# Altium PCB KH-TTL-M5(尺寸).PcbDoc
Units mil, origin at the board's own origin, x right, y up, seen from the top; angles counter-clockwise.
Board outline 6000 x 4000 mil, 2 copper layers (Top Layer, Bottom Layer); 2 components, 28 nets, 12 pads, 0 vias.
Unrouted connection lines stored in the file: 3.
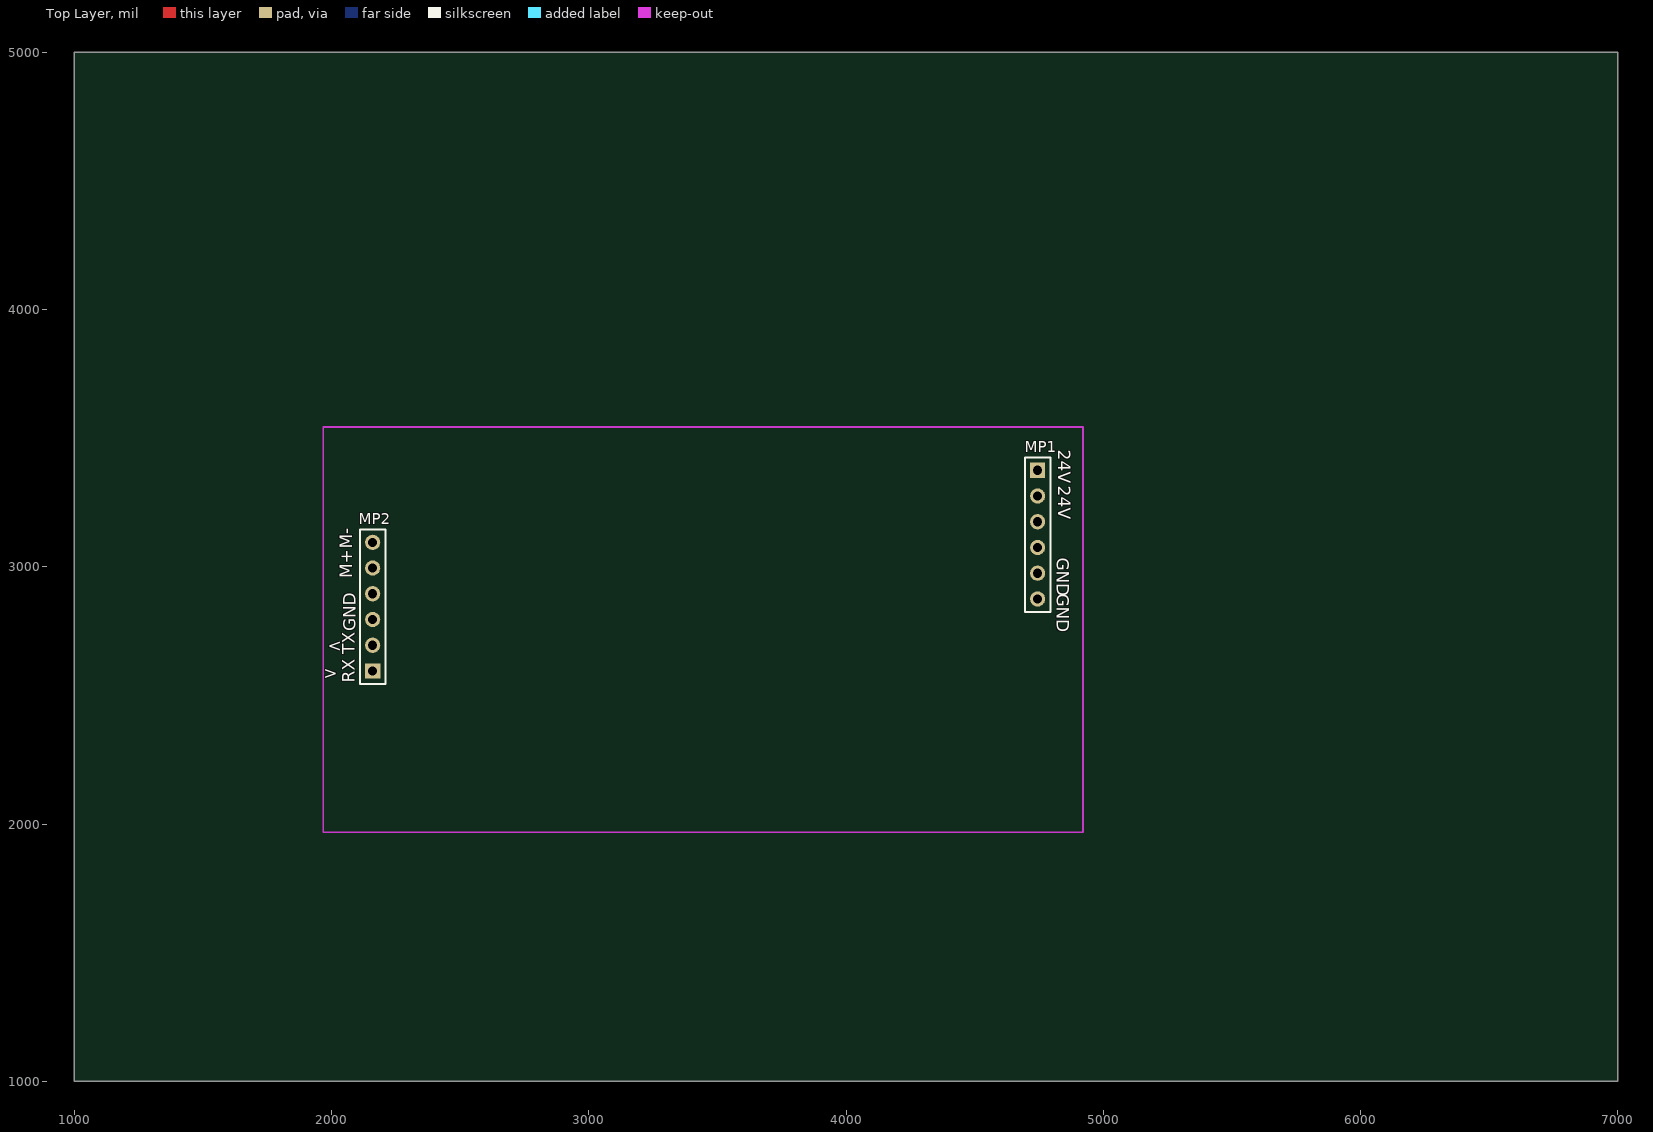
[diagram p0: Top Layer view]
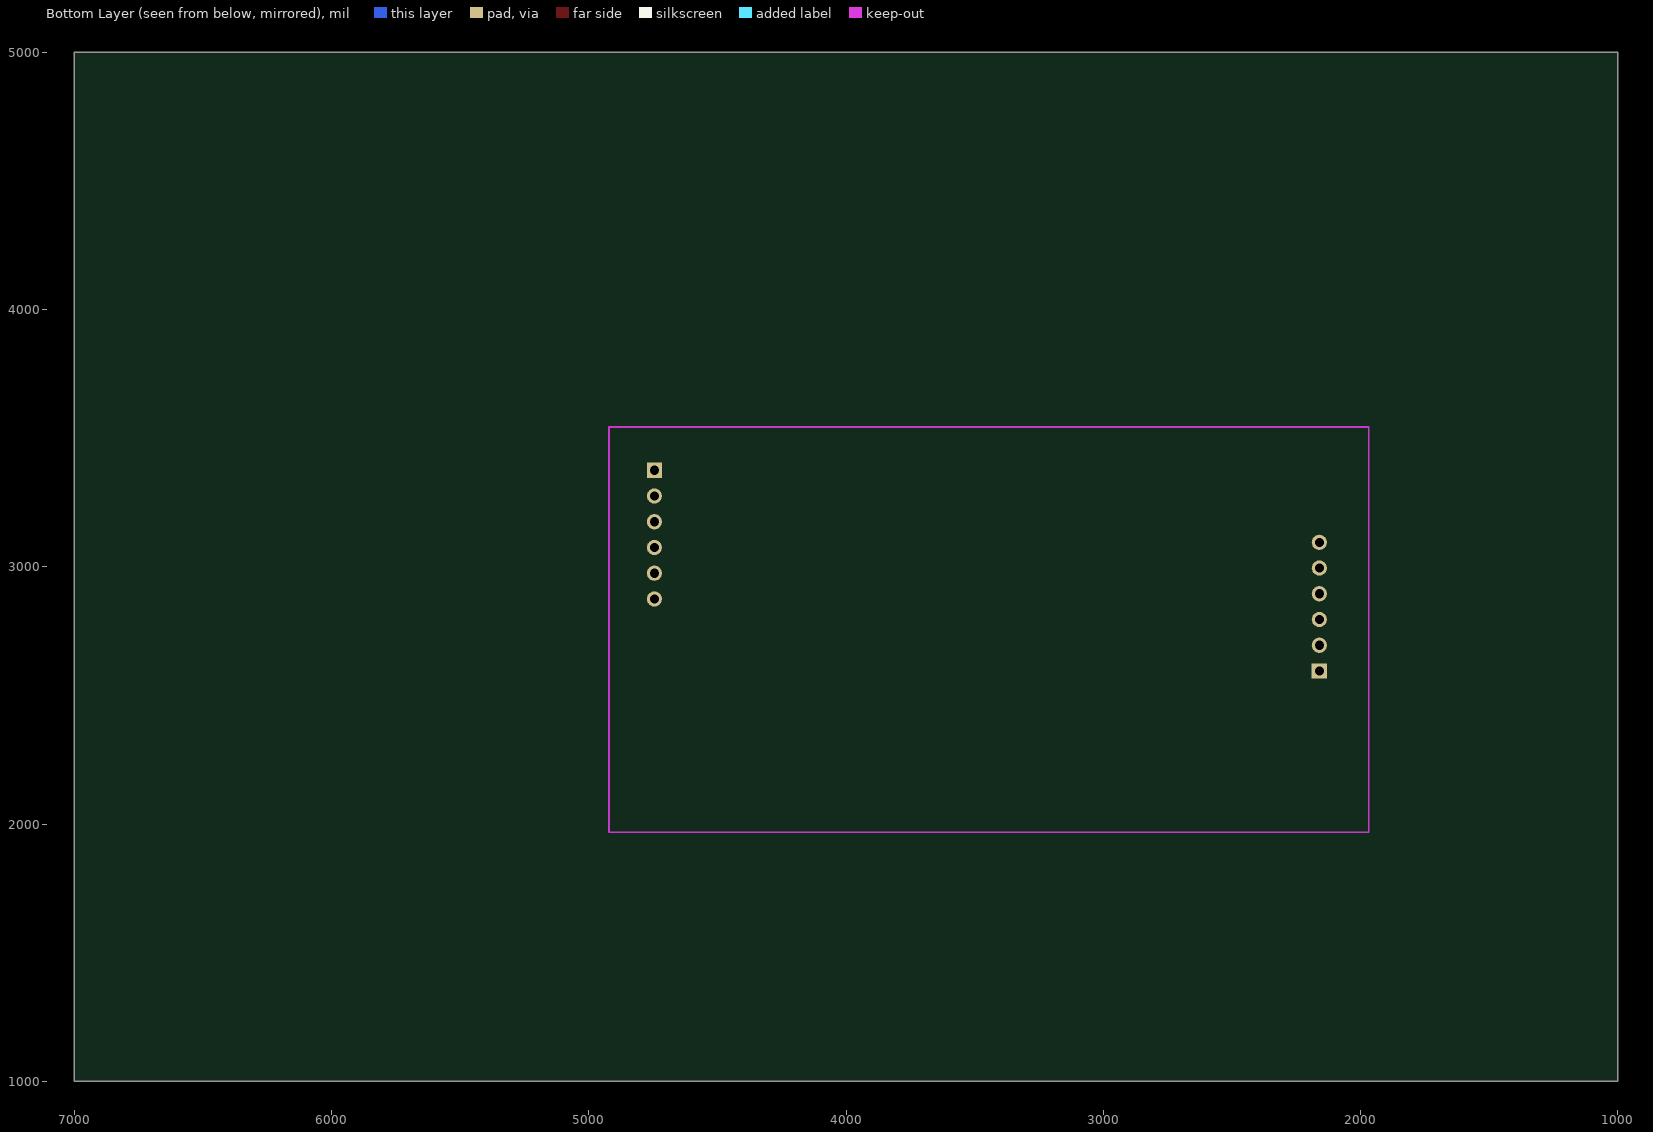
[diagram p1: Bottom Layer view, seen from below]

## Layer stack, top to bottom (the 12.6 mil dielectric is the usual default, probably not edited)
Top Layer: signal copper 1.4
Dielectric: dielectric 12.6, FR-4, Dk 4.8
Bottom Layer: signal copper 1.4

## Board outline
1000,1000 7000,1000 7000,5000 1000,5000

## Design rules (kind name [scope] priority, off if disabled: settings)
Clearance Clearance_1 [InPoly] p1: gap=15
Clearance [All] p2: gap=8
HoleSize [All] p1: absolutevalues=TRUE maxlimit=500 minlimit=0 maxpercent=80.000 minpercent=20.000
MinimumSolderMaskSliver [All] p1: minsoldermaskwidth=0
PolygonConnect [All] p1: connectstyle=Relief reliefconductorwidth=10 reliefentries=4 polygonreliefangle="90 Angle"
RoomDefinition LY_MBUS [InComponentClass('LY_MBUS')] p1: confinementstyle=ConfineIn formatcopy=TRUE lockcomponents=FALSE outline 230,195 7920,195 7920,5655 230,5655
RoutingVias [All] p1: holewidth=24 width=50 viastyle="Through Hole" minholewidth=16 minwidth=40 maxholewidth=50 maxwidth=100
SilkToSilkClearance [All] p1: silktosilkclearance=0
SilkscreenOverComponentPads [All] p1: minsilkscreentomaskgap=0
SolderMaskExpansion [All] p1: expansion=4
Width [All] p1: maxlimit=50 minlimit=8 preferedwidth=10
24 further rules are at their usual default settings.

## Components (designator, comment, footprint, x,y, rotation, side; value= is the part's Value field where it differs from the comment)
MP1 "Header 6" HDR1X6 4745,3375 r270 top
MP2 "Header 6" HDR1X6 2160,2595 r90 top

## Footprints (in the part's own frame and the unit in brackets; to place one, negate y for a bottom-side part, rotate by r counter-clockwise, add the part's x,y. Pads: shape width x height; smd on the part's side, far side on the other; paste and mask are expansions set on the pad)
HDR1X6 [mm] "Connector; Header; 6 Position"
  rect 1.5x1.5 hole 0.9: 1(0,0)
  round 1.5 hole 0.9: 2(2.54,0) 3(5.08,0) 4(7.62,0) 5(10.16,0) 6(12.7,0)
  silkscreen extent -1.27,-1.27 13.97,1.27

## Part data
MP1 MP2: "Header, 6-Pin"

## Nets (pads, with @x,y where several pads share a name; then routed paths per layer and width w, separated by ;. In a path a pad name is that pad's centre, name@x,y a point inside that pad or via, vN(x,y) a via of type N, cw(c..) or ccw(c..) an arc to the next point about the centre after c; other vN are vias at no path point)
5V: 
24V: MP1.1 MP1.2
+5V: 
-12V: MP2.6
GND: MP1.5 MP1.6 MP2.3
M+: MP2.5
NetC4_2: 
NetCT1_1: 
NetCT2_1: 
NetD2_2: 
NetD3_2: 
NetD4_2: 
NetF1_2: 
NetN1_1: 
NetN1_3: 
NetN2_3: 
NetN3_1: 
NetN3_2: 
NetN4_1: 
NetPWR_2: 
NetQ1_3: 
NetR1_1: 
NetR2_1: 
NetR4_2: 
NetR5_1: 
NetR17_2: 
ROUT: MP2.1
RXD3: MP2.2
pads on no net: MP1.3 MP1.4 MP2.4

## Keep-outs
Keep-Out Layer:
  lines w6: 1968.5,1968.5 4921.26,1968.5 4921.26,3543.31 1968.5,3543.31 1968.5,1968.5

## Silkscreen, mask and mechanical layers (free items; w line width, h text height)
Top Overlay:
  text "24V" at 4825,3455 h48 r270
  text "24V" at 4825,3315 h48 r270
  text "M-" at 2080,3070 h48 r90
  text "GND" at 4820,3035 h48 r270
  text "M+" at 2080,2955 h48 r90
  text "GND" at 4820,2895 h48 r270
  text "GND" at 2095,2750 h48 r90
  text "<" at 1985,2670 h48
  text "TX" at 2090,2660 h48 r90
  text "<" at 2025,2605 h48 r180
  text "RX" at 2090,2550 h48 r90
